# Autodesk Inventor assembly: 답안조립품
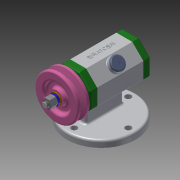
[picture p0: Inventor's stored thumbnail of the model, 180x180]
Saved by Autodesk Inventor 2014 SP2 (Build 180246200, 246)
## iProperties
Created: 2021-02
Part Number: 답안조립품
Document SubType Name: Assembly
Designer: 거성
Author: 거성
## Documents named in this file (14)
- C:\Users\거성\Desktop\710204V1005\답안조립품.iam
- C:\Users\거성\Desktop\710204V1005\본체.ipt
- C:\Users\거성\Desktop\710204V1005\베어링 15 x 32 x 9.ipt
- C:\Users\거성\Desktop\710204V1005\뒤커버.ipt
- C:\Users\거성\Desktop\710204V1005\앞커버.ipt
- C:\Users\거성\Desktop\710204V1005\오일 실 15 25 7.ipt
- C:\Users\거성\Desktop\710204V1005\볼트 M4 x 12.ipt
- C:\Users\거성\Desktop\710204V1005\축.ipt
- C:\Users\거성\Desktop\710204V1005\키 3 x 3 x 12.ipt
- C:\Users\거성\Desktop\710204V1005\V벨트풀리.ipt
- C:\Users\거성\Desktop\710204V1005\와셔 8x17.ipt
- C:\Users\거성\Desktop\710204V1005\스프링와셔 8.ipt
- C:\Users\거성\Desktop\710204V1005\너트 M8.ipt
- C:\Users\거성\Desktop\710204V1005\고무캡.ipt
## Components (2 placed, 2 different names)
1. V벨트풀리:1
2. 고무캡:1
